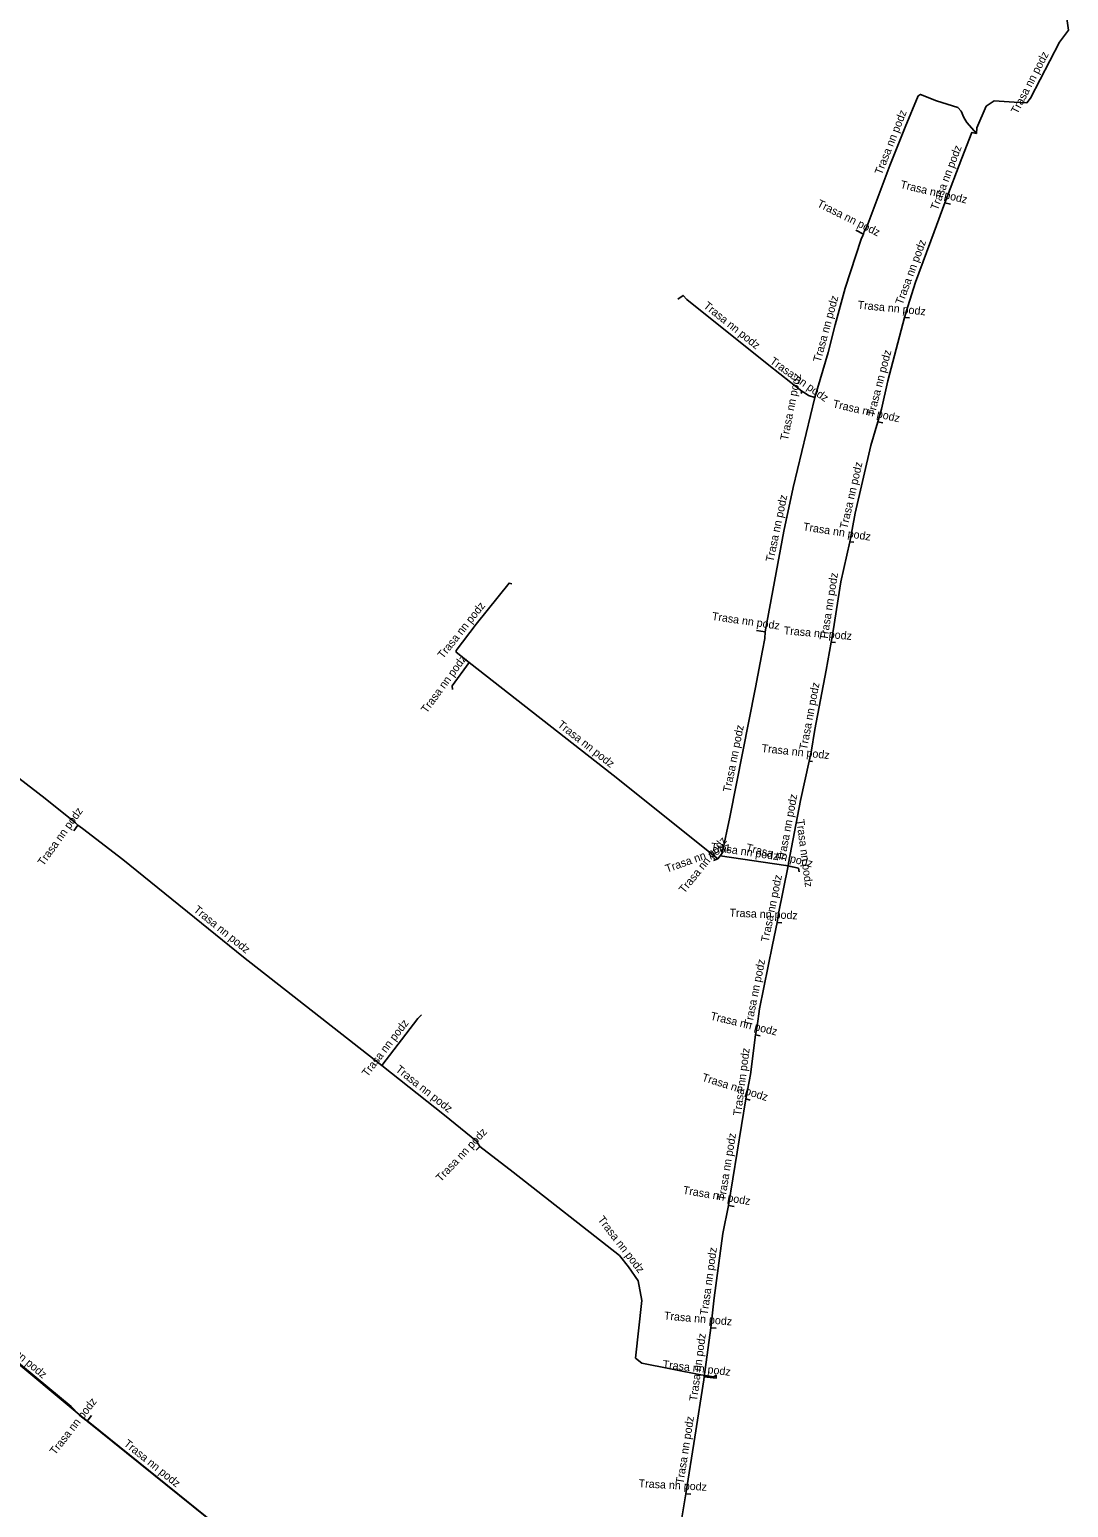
# Model space of a CAD drawing. Extents: x -737281 to -735046, y -1033441 to -1031241.
# Drawn here: x -735748.3 to -735618.5, y -1032757.1 to -1032572.3 of the extents above; entities that cross this region are included whole.
import ezdxf

# ---------------------------------------------------------------- set-up
doc = ezdxf.new("R2010")
doc.units = 0
for name, color, linetype in [('Level 11', 7, 'Continuous'), ('Level 20', 7, 'Continuous'), ('Level 21', 7, 'Continuous')]:
    doc.layers.add(name, color=color, linetype=linetype)

msp = doc.modelspace()

# ---------------------------------------------------------------- linework, layer by layer
at = {"layer": 'Level 11'}
for p, q in [((-735633.94, -1032593.99), (-735633.23, -1032594.15)), ((-735644.11, -1032597.9), (-735645.08, -1032597.42)), ((-735639, -1032608.31), (-735638.37, -1032608.37)), ((-735651.83, -1032617.54), (-735651.89, -1032617.85)), ((-735642.31, -1032621.36), (-735641.7, -1032621.49)), ((-735645.84, -1032636.35), (-735645.34, -1032636.42)), ((-735656.42, -1032647.6), (-735657.49, -1032647.45)), ((-735648.18, -1032648.93), (-735647.62, -1032648.97)), ((-735650.92, -1032663.78), (-735650.48, -1032663.82)), ((-735742.78, -1032672.48), (-735742.29, -1032671.8)), ((-735662.32, -1032675.99), (-735662.86, -1032676.19)), ((-735662.03, -1032675.63), (-735662.32, -1032675.99)), ((-735652.23, -1032677.18), (-735653.54, -1032676.85)), ((-735652.17, -1032677.64), (-735652.23, -1032677.18)), ((-735654.92, -1032683.96), (-735654.34, -1032683.98)), ((-735657.61, -1032697.98), (-735657.05, -1032698.11)), ((-735661, -1032719.34), (-735658.81, -1032706)), ((-735658.81, -1032706), (-735658.27, -1032706.18)), ((-735692.05, -1032711.95), (-735692.5, -1032712.43)), ((-735661, -1032719.34), (-735660.27, -1032719.46)), ((-735756.33, -1032733.61), (-735741.14, -1032746.28)), ((-735664.01, -1032740.75), (-735663.21, -1032734.6)), ((-735663.21, -1032734.6), (-735662.54, -1032734.66)), ((-735741.14, -1032746.28), (-735740.59, -1032745.58)), ((-735741.14, -1032746.28), (-735722.97, -1032760.91)), ((-735666.3, -1032755.36), (-735665.68, -1032755.39))]:
    msp.add_line(p, q, dxfattribs=at)
for points in [[(-735629.98, -1032585.31), (-735629.94, -1032584.62), (-735628.78, -1032581.92), (-735627.78, -1032581.26), (-735625.29, -1032581.41), (-735623.7, -1032581.49), (-735623.24, -1032580.91), (-735619.61, -1032573.93), (-735618.51, -1032572.43), (-735618.8, -1032570.39), (-735621.51, -1032568.59), (-735621.54, -1032568.15), (-735620.82, -1032566.77)], [(-735629.98, -1032585.31), (-735631.19, -1032583.95), (-735631.57, -1032583.33), (-735631.92, -1032582.55), (-735632.35, -1032582.08), (-735635.01, -1032581.25), (-735636.98, -1032580.45), (-735637.29, -1032580.64), (-735638.92, -1032584.55), (-735640.82, -1032589.35), (-735643.71, -1032596.98), (-735644.02, -1032597.59), (-735644.11, -1032597.9)], [(-735633.94, -1032593.99), (-735631.82, -1032588.42), (-735630.57, -1032585.2), (-735629.98, -1032585.31)], [(-735633.94, -1032593.99), (-735635.29, -1032597.63), (-735637.64, -1032603.93), (-735638.59, -1032606.97), (-735639, -1032608.31)], [(-735650.2, -1032618.33), (-735648.52, -1032612.71), (-735647.67, -1032609.23), (-735646.43, -1032604.66), (-735644.39, -1032598.55), (-735644.22, -1032598.1), (-735644.11, -1032597.9)], [(-735651.83, -1032617.54), (-735655.96, -1032614.27), (-735666.21, -1032606.06), (-735666.66, -1032605.57), (-735667.33, -1032606.03)], [(-735639, -1032608.31), (-735641.08, -1032616.24), (-735641.85, -1032619.77), (-735642.31, -1032621.36)], [(-735656.42, -1032647.6), (-735654.06, -1032635.05), (-735652.91, -1032629.59), (-735650.2, -1032618.33)], [(-735650.2, -1032618.33), (-735651.01, -1032618.07), (-735651.42, -1032617.79), (-735651.83, -1032617.54)], [(-735642.31, -1032621.36), (-735643.22, -1032624.32), (-735645.17, -1032632.78), (-735645.55, -1032634.83), (-735645.84, -1032636.35)], [(-735645.84, -1032636.35), (-735646.96, -1032641.35), (-735647.92, -1032647.48), (-735648.18, -1032648.93)], [(-735693.38, -1032651.45), (-735695.01, -1032650.18), (-735695.03, -1032649.94), (-735692.52, -1032646.68), (-735688.41, -1032641.52), (-735688.05, -1032641.6)], [(-735662.03, -1032675.63), (-735661.8, -1032675.3), (-735660.83, -1032670.8), (-735657.6, -1032654.57), (-735656.72, -1032649.95), (-735656.46, -1032648.44), (-735656.42, -1032647.6)], [(-735648.18, -1032648.93), (-735648.79, -1032652.42), (-735650.19, -1032659.82), (-735650.64, -1032662.66), (-735650.92, -1032663.78)], [(-735693.38, -1032651.45), (-735695.51, -1032654.36), (-735695.48, -1032654.83)], [(-735662.32, -1032675.99), (-735675.4, -1032665.55), (-735693.38, -1032651.45)], [(-735742.29, -1032671.8), (-735742.58, -1032671.51), (-735746.37, -1032668.44), (-735755.38, -1032661.54), (-735755.34, -1032661.17), (-735750.94, -1032655.53)], [(-735650.92, -1032663.78), (-735652.01, -1032668.72), (-735653.48, -1032676.53), (-735653.54, -1032676.85)], [(-735704.32, -1032701.83), (-735721.58, -1032688.28), (-735736.66, -1032676.09), (-735741.73, -1032672.21), (-735742.29, -1032671.8)], [(-735652.23, -1032677.18), (-735653.82, -1032676.81), (-735662.03, -1032675.63)], [(-735653.54, -1032676.85), (-735654.74, -1032682.84), (-735654.92, -1032683.96)], [(-735654.92, -1032683.96), (-735655.51, -1032686.75), (-735657.12, -1032694.75), (-735657.39, -1032696.93), (-735657.61, -1032697.98)], [(-735704.32, -1032701.83), (-735699.8, -1032695.95), (-735699.37, -1032695.5)], [(-735657.61, -1032697.98), (-735658.25, -1032702.95), (-735658.81, -1032706)], [(-735692.05, -1032711.95), (-735692.47, -1032711.3), (-735696.47, -1032708.02), (-735704.32, -1032701.83)], [(-735662.55, -1032740.52), (-735662.83, -1032740.76), (-735664.45, -1032740.49), (-735671.83, -1032739.04), (-735672.62, -1032738.39), (-735671.81, -1032731.19), (-735672.26, -1032728.73), (-735673.49, -1032727), (-735674.59, -1032725.58), (-735687.88, -1032715.18), (-735692.05, -1032711.95)], [(-735661, -1032719.34), (-735661.68, -1032722.81), (-735662.79, -1032730.88), (-735663.21, -1032734.6)], [(-735666.3, -1032755.36), (-735665.19, -1032748.3), (-735664.07, -1032741.11), (-735664.01, -1032740.75)], [(-735662.55, -1032740.52), (-735662.54, -1032740.92), (-735664.01, -1032740.75)], [(-735666.3, -1032755.36), (-735666.88, -1032758.61), (-735667.91, -1032766.18), (-735668.42, -1032770.66)]]:
    msp.add_lwpolyline(points, dxfattribs=at)
at = {"layer": 'Level 21'}
msp.add_lwpolyline([(-735753.62, -1032735.77), (-735743.13, -1032744.46), (-735742.08, -1032745.52), (-735740.79, -1032746.5), (-735721.39, -1032762.18)], dxfattribs=at)

# ---------------------------------------------------------------- texts
at = {"layer": 'Level 20'}
for rotation, p in [(62.523, (-735624.88, -1032582.98)), (68.4066, (-735641.84, -1032590.57)), (69.1964, (-735634.86, -1032595.01)), (346.764, (-735639.59, -1032592.14)), (333.6239, (-735650.01, -1032594.42)), (69.5446, (-735639.25, -1032606.82)), (74.8203, (-735649.48, -1032613.99)), (354.2357, (-735644.89, -1032607.21)), (321.3286, (-735664.2, -1032607.03)), (324.7713, (-735655.91, -1032614)), (75.3471, (-735642.78, -1032620.78)), (78.7619, (-735653.57, -1032623.77)), (347.3017, (-735648.03, -1032619.56)), (77.0479, (-735646.15, -1032634.82)), (78.1076, (-735655.39, -1032638.95)), (351.2452, (-735651.73, -1032634.93)), (81.0432, (-735648.63, -1032648.74)), (51.4487, (-735696.66, -1032651.06)), (351.7872, (-735663.11, -1032646.13)), (355.1421, (-735654.12, -1032647.92)), (53.8315, (-735698.7, -1032657.87)), (79.2976, (-735651.19, -1032662.44)), (321.8974, (-735682.44, -1032659.39)), (78.7458, (-735660.73, -1032667.74)), (353.9709, (-735656.9, -1032662.64)), (79.3719, (-735653.96, -1032676.39)), (54.3675, (-735746.6, -1032676.96)), (277.4635, (-735652.52, -1032671.11)), (19.7135, (-735668.68, -1032677.74)), (51.0275, (-735666.51, -1032680.39)), (351.8161, (-735663.27, -1032674.95)), (346.1593, (-735658.87, -1032675.03)), (78.6569, (-735655.98, -1032686.47)), (321.048, (-735727.92, -1032682.52)), (357.6141, (-735660.89, -1032683.21)), (78.6143, (-735658.08, -1032697.02)), (52.4993, (-735706.1, -1032703.32)), (346.3025, (-735663.32, -1032696.07)), (82.641, (-735659.43, -1032708.17)), (321.7233, (-735702.68, -1032702.48)), (342.5199, (-735664.39, -1032703.72)), (46.9456, (-735696.93, -1032716.44)), (80.6841, (-735661.42, -1032718.79)), (350.3353, (-735666.75, -1032717.85)), (307.6599, (-735677.4, -1032721.11)), (82.2063, (-735663.59, -1032733.1)), (354.8978, (-735669.09, -1032733.57)), (320.1833, (-735753.24, -1032735.54)), (82.5555, (-735664.92, -1032743.84)), (353.3988, (-735669.26, -1032739.64)), (52.125, (-735745.12, -1032750.59)), (81.1118, (-735666.62, -1032754.19)), (321.1464, (-735736.64, -1032749.26)), (356.9434, (-735672.24, -1032754.54))]:
    msp.add_text('Trasa nn podz', height=1, rotation=rotation, dxfattribs=at).set_placement(p)

doc.saveas('drawing.dxf')
